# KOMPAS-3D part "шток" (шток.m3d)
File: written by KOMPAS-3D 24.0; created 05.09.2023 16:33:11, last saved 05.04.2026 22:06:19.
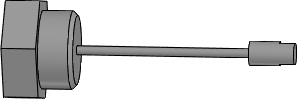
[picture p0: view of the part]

Document properties: Полное имя файла: E:\Работа\Зайцев\Аксессуары для пневмоприводов\Электропневматические позиционеры DN.ru\ЭИП Электропневматический позиционер DN.ru\ЭИП-1500 Электропневматический позиционер DN.ru\25-50\исходные материалы\шток.m3d

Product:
- Part/product: шток
    Масса: 0.136404

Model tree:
1. Операция без истории:1
2. Эскиз:1  (with: Грань.Операция без истории:1)
3. Элемент выдавливания:1
     Расстояние 2 = 107.1
4. Эскиз:2
5. Элемент выдавливания:2
6. Эскиз:3
7. Элемент вращения:1
     Угол 1 = 360
8. Эскиз:4  (with: Грань.Элемент вращения:1)
9. Элемент выдавливания:3
10. Фаска:1  (with: Ребро.Элемент вращения:1)
     Угол = 45; Длина 1 = 1.5; Длина 2 = 1.5
11. Эскиз:5  (with: Грань.Элемент вращения:1)
12. Элемент выдавливания:4
     Расстояние 2 = 5

Expressions: 8.5+3; 84-v81/2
